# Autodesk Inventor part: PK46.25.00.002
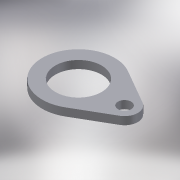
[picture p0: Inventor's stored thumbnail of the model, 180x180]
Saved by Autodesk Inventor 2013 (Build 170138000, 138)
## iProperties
Created: 2005-05
Part Number: PK46.25.00.002
Material: Steel, Mild
Document SubType Name: Modeling
Designer: PVitaliy
Manufacturer: Standard
Standards Organization: Custom
Density: 7.86 g/cm^3
Author: PVitaliy
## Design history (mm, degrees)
sketch "Эскиз2"
  geometry: L1 (0, 0)-(70, 0); L2 (27.5, 47.631)-(80, 17.321); L3 (80, -17.321)-(27.5, -47.631); C1 r 35 at (0, 0); C2 r 10 at (70, 0); A1 r 55 centre (0, 0) between (27.5, 47.631) and (27.5, -47.631); A2 r 20 centre (70, 0) between (80, -17.321) and (80, 17.321)
  constraints: 6 end point, 4 centre point, 4 point on circle, 4 tangent, 3 coincident, 1 horizontal, 1 other
  dimensions: "d0" = 70 distance of L1.start L1.end; "d1" = 55 radius of A1; "d2" = 70 diameter of C1; "d3" = 20 radius of A2; "d4" = 20 diameter of C2
extrude "Выдавливание1" new body sketch "Эскиз2" distance "d5" = 12; taper "d6" = 0 deg
body "Solid1"
